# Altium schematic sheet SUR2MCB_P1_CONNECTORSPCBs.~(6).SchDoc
size 420 x 297 mm; Scale: 1:1; Разраб.: Иванов; Обозначение документа: АБВГ.123456.001 Э3; Пров.: Петров; Утв.: Сидоров; Наименование организации: ОАО "Концерн "МПО-Гидроприбор"; Перв. применение: АБВГ.123456.000; Наименование изделия 1: Плата; Наименование изделия 2: Схема электрическая; Наименование изделия 3: принципиальная; Нач. отд.: Нач. отд.; Фамилия нач. отд.: Сидоров
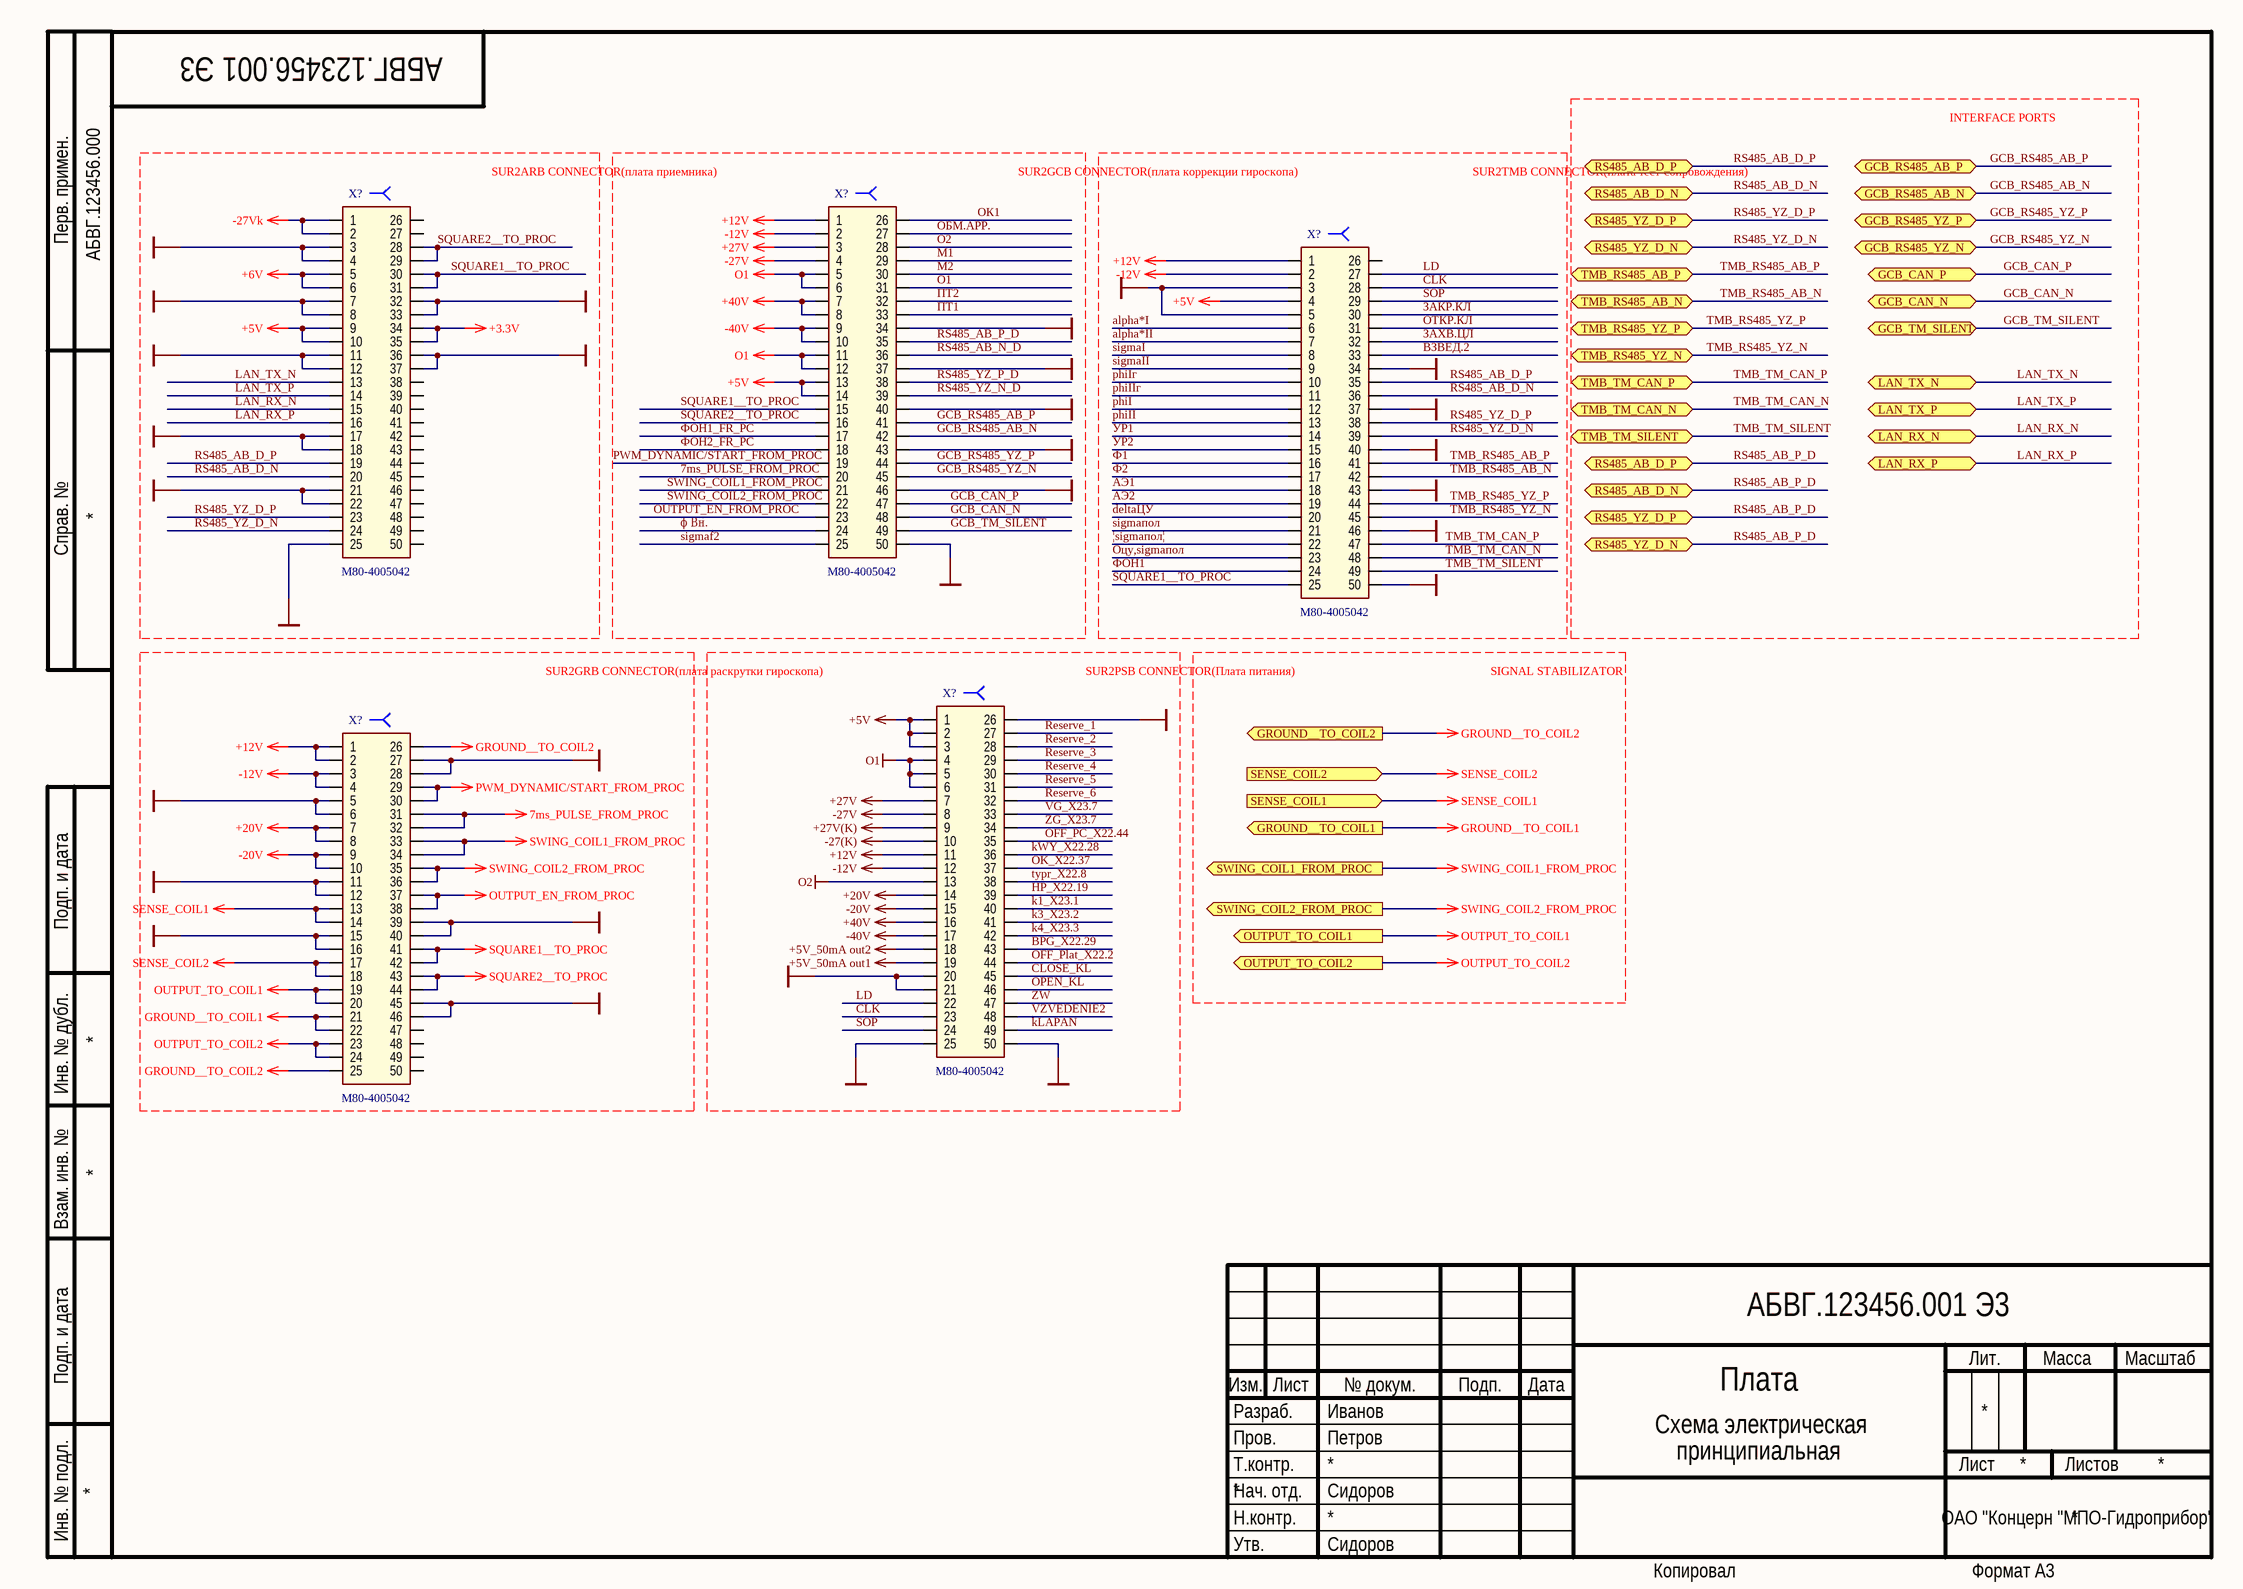
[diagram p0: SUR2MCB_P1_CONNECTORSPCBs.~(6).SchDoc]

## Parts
(Parts that share a designator on the sheet are numbered #1, #2 ... from top to bottom, then left to right.)
X?#1  value M80-4005042  [M80-4005042]
X?#2  value M80-4005042  [M80-4005042]
X?#3  value M80-4005042  [M80-4005042]
X?#4  value M80-4005042  [M80-4005042]
X?#5  value M80-4005042  [M80-4005042]

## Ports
GCB_CAN_N (bidir), GCB_CAN_P (bidir), GCB_RS485_AB_N (bidir), GCB_RS485_AB_P (bidir), GCB_RS485_YZ_N (bidir), GCB_RS485_YZ_P (bidir), GCB_TM_SILENT (bidir), GROUND__TO_COIL1 (out), GROUND__TO_COIL2 (out), LAN_RX_N (bidir), LAN_RX_P (bidir), LAN_TX_N (bidir), LAN_TX_P (bidir), OUTPUT_TO_COIL1 (out), OUTPUT_TO_COIL2 (out), RS485_AB_D_N (bidir), RS485_AB_D_P (bidir), RS485_YZ_D_N (bidir), RS485_YZ_D_P (bidir), SENSE_COIL1 (in), SENSE_COIL2 (in), SWING_COIL1_FROM_PROC (out), SWING_COIL2_FROM_PROC (out), TMB_RS485_AB_N (bidir), TMB_RS485_AB_P (bidir), TMB_RS485_YZ_N (bidir), TMB_RS485_YZ_P (bidir), TMB_TM_CAN_N (bidir), TMB_TM_CAN_P (bidir), TMB_TM_SILENT (bidir)

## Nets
7ms_PULSE_FROM_PROC: X?#2.20 X?#5.31 X?#5.32
+3.3V: X?#1.34 X?#1.35
+5V: X?#1.9 X?#1.10 X?#2.13 X?#2.14 X?#3.4 X?#4.1 X?#4.2 X?#4.3
+5V_50mA out1: X?#4.19
+5V_50mA out2: X?#4.18
+6V: X?#1.5 X?#1.6
+12V: X?#2.1 X?#3.1 X?#4.11 X?#5.1 X?#5.2
+20V: X?#4.14 X?#5.7 X?#5.8
+27V: X?#2.3 X?#4.7
+27V(K): X?#4.9
+40V: X?#2.7 X?#2.8 X?#4.16
-12V: X?#2.2 X?#3.2 X?#4.12 X?#5.3 X?#5.4
-20V: X?#4.15 X?#5.9 X?#5.10
-27(K): X?#4.10
-27V: X?#2.4 X?#4.8
-27Vk: X?#1.1 X?#1.2
-40V: X?#2.9 X?#2.10 X?#4.17
GND: X?#1.3 X?#1.4 X?#1.7 X?#1.8 X?#1.11 X?#1.12 X?#1.17 X?#1.18 X?#1.21 X?#1.22 X?#1.25 X?#1.32 X?#1.33 X?#1.36 X?#1.37 X?#2.34 X?#2.37 X?#2.40 X?#2.43 X?#2.46 X?#2.50 X?#3.3 X?#3.5 X?#3.34 X?#3.37 X?#3.40 X?#3.43 X?#3.46 X?#3.50 X?#4.20 X?#4.21 X?#4.25 X?#4.26 X?#4.50 X?#5.5 X?#5.6 X?#5.11 X?#5.12 X?#5.15 X?#5.16 X?#5.27 X?#5.28 X?#5.39 X?#5.40 X?#5.45 X?#5.46
GROUND__TO_COIL1: X?#5.21 X?#5.22 ; port GROUND__TO_COIL1
GROUND__TO_COIL2: X?#5.25 X?#5.26 ; port GROUND__TO_COIL2
OUTPUT_EN_FROM_PROC: X?#2.23 X?#5.37 X?#5.38
OUTPUT_TO_COIL1: X?#5.19 X?#5.20 ; port OUTPUT_TO_COIL1
OUTPUT_TO_COIL2: X?#5.23 X?#5.24 ; port OUTPUT_TO_COIL2
PWM_DYNAMIC/START_FROM_PROC: X?#2.19 X?#5.29 X?#5.30
SENSE_COIL1: X?#5.13 X?#5.14 ; port SENSE_COIL1
SENSE_COIL2: X?#5.17 X?#5.18 ; port SENSE_COIL2
SQUARE1__TO_PROC: X?#1.30 X?#1.31 X?#2.15 X?#3.25 X?#5.41 X?#5.42
SQUARE2__TO_PROC: X?#1.28 X?#1.29 X?#2.16 X?#5.43 X?#5.44
SWING_COIL1_FROM_PROC: X?#2.21 X?#5.33 X?#5.34 ; port SWING_COIL1_FROM_PROC
SWING_COIL2_FROM_PROC: X?#2.22 X?#5.35 X?#5.36 ; port SWING_COIL2_FROM_PROC
О1: X?#2.5 X?#2.6 X?#2.11 X?#2.12 X?#2.31 X?#4.4 X?#4.5 X?#4.6
О2: X?#2.28 X?#4.13
alpha*I: X?#3.6
alpha*II: X?#3.7
BPG_X22.29: X?#4.43
CLK: X?#3.28 X?#4.23
CLOSE_KL: X?#4.45
deltaЦУ: X?#3.20
GCB_CAN_N: X?#2.48 ; port GCB_CAN_N
GCB_CAN_P: X?#2.47 ; port GCB_CAN_P
GCB_RS485_AB_N: X?#2.42 ; port GCB_RS485_AB_N
GCB_RS485_AB_P: X?#2.41 ; port GCB_RS485_AB_P
GCB_RS485_YZ_N: X?#2.45 ; port GCB_RS485_YZ_N
GCB_RS485_YZ_P: X?#2.44 ; port GCB_RS485_YZ_P
GCB_TM_SILENT: X?#2.49 ; port GCB_TM_SILENT
HP_X22.19: X?#4.39
k1_X23.1: X?#4.40
k3_X23.2: X?#4.41
k4_X23.3: X?#4.42
kLAPAN: X?#4.49
kWY_X22.28: X?#4.36
LAN_RX_N: X?#1.15 ; port LAN_RX_N
LAN_RX_P: X?#1.16 ; port LAN_RX_P
LAN_TX_N: X?#1.13 ; port LAN_TX_N
LAN_TX_P: X?#1.14 ; port LAN_TX_P
LD: X?#3.27 X?#4.22
OFF_PC_X22.44: X?#4.35
OFF_Plat_X22.2: X?#4.44
OK_X22.37: X?#4.37
OPEN_KL: X?#4.46
phiI: X?#3.12
phiII: X?#3.13
phiIIг: X?#3.11
phiIг: X?#3.10
Reserve_1: X?#4.27
Reserve_2: X?#4.28
Reserve_3: X?#4.29
Reserve_4: X?#4.30
Reserve_5: X?#4.31
Reserve_6: X?#4.32
RS485_AB_D_N: X?#1.19 X?#1.20 X?#1.23 X?#1.24 X?#2.35 X?#3.35 X?#3.36 X?#3.38 X?#3.39 ; port RS485_AB_D_P, port RS485_AB_D_N, port RS485_YZ_D_P, port RS485_YZ_D_N  [also labelled RS485_AB_D_P, RS485_AB_P_D, RS485_YZ_D_N, RS485_YZ_D_P]
RS485_AB_N_D: X?#2.36
RS485_YZ_N_D: X?#2.39
RS485_YZ_P_D: X?#2.38
sigmaf2: X?#2.25
sigmaI: X?#3.8
sigmaII: X?#3.9
sigmaпол: X?#3.21
SOP: X?#3.29 X?#4.24
TMB_RS485_AB_N: X?#3.42 ; port TMB_RS485_AB_N
TMB_RS485_AB_P: X?#3.41 ; port TMB_RS485_AB_P
TMB_RS485_YZ_N: X?#3.45 ; port TMB_RS485_YZ_N
TMB_RS485_YZ_P: X?#3.44 ; port TMB_RS485_YZ_P
TMB_TM_CAN_N: X?#3.48 ; port TMB_TM_CAN_N
TMB_TM_CAN_P: X?#3.47 ; port TMB_TM_CAN_P
TMB_TM_SILENT: X?#3.49 ; port TMB_TM_SILENT
typr_X22.8: X?#4.38
VG_X23.7: X?#4.33
VZVEDENIE2: X?#4.48
ZG_X23.7: X?#4.34
ZW: X?#4.47
¦sigmaпол¦: X?#3.22
ϕ Вн.: X?#2.24
АЭ1: X?#3.18
АЭ2: X?#3.19
ВЗВЕД.2: X?#3.33
ЗАКР.КЛ: X?#3.30
ЗАХВ.ЦЛ: X?#3.32
М1: X?#2.29
М2: X?#2.30
ОБМ.АРР.: X?#2.27
ОК1: X?#2.26
ОТКР.КЛ: X?#3.31
Оцу,sigmaпол: X?#3.23
ПТ1: X?#2.33
ПТ2: X?#2.32
УР1: X?#3.14
УР2: X?#3.15
Ф1: X?#3.16
Ф2: X?#3.17
ФОН1: X?#3.24
ФОН1_FR_PC: X?#2.17
ФОН2_FR_PC: X?#2.18

Not connected (* = marked no-connect by the designer): X?#1 26 27 38 39 40 41 42 43 44 45 46 47 48 49 50; X?#3 26; X?#5 47 48 49 50

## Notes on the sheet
- INTERFACE PORTS
- (near X?#1) SUR2ARB CONNECTOR(плата приемника)
- (near X?#2) SUR2GCB CONNECTOR(плата коррекции гироскопа)
- SUR2TMB CONNECTOR(плата тест-сопровождения)
- SUR2GRB CONNECTOR(плата раскрутки гироскопа)
- (near X?#4) SUR2PSB CONNECTOR(Плата питания)
- SIGNAL STABILIZATOR

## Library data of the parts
X?#1-X?#5 = M80-4005042: 25+25 WAY FEMALE PC TAIL 3MM; ValueManufacturer: Harwin Inc.; PowerVoltage: 120V; TechSpec: 3A; ValueDescription: M80-4005042 Розетка Harwin Inc.  5.55x60mm  3A; ValueType: Female Socket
